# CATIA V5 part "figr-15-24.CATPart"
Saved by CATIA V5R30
Part number: Part1
Bounding box of the stored display mesh (mm): x -50 to 50, y -25 to 25, z -24 to 1
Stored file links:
  D:\PROJECTS\CATIA V56R 2020\Resources\Parts File\c15_catia_v5_6r2020_prt\figr-15-24.CATPart
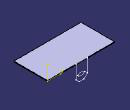
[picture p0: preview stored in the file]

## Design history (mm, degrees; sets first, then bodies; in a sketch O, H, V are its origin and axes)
SheetMetalParameters1: Thickness 1, BendRadius 2, KFactor 0.400515 {= log(min(100,max(20*SheetMetalParameters1.BendRadius,SheetMetalParameters1.Thickness)/SheetMetalParameters1.Thickness))/log(100)/2}, ReliefRadialLength 1, ReliefAxialLength 2, MinimumBendRadius 0
Body1 (main body)
  Sketch1 on xy-plane, origin (0, 0, 0), H (1, 0, 0), V (0, 1, 0)
    line L1 (-50, 25) -> (50, 25)
    line L2 (50, 25) -> (50, -25)
    line L3 (50, -25) -> (-50, -25)
    line L4 (-50, -25) -> (-50, 25)
    length L1 = 100
    distance V L2 = 50
    length L2 = 50
    distance H L3 = 25
    horizontal: L1 H, L3 H
    vertical: L2 V, L4 V
  Wall1: Thickness 1, Profile Sketch1
  Sketch2 on face of Wall1, origin (50, 25, 0), H (-1, 0, 0), V (0, 0, 1)
    line L1 (42.3549, 1) -> (42.3549, -19)
    point P2 (42.3549, -19)
    line L2 (42.3549, -19) -> (47.3549, -24)
    point P3 (47.3549, -24)
    line L3 (47.3549, -24) -> (54.3549, -24)
    point P4 (54.3549, -24)
    line L4 (54.3549, -24) -> (59.3549, -19)
    point P5 (59.3549, -19)
    line L5 (59.3549, -19) -> (59.3549, 1)
    line L6 (59.3549, 1) -> (42.3549, 1)
    reference projected line E1 (100, 1) -> (0, 1) from edge [face of Wall1 | face of Wall1]
    ellipse A1 centre (50.1164, -15.2153) semi-axes 5.0583, 2.1402 rotation 0
    length L5 = 20
    length L1 = 20
    length L3 = 7
    distance P4 L5 = 5
    distance P2 P3 H = 5
    distance L3 P5 = 5
    vertical: L1 V, L5 V
    horizontal: L3 H, L6 H
    coincidence: L6 E1
    parallelism: A1 L3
